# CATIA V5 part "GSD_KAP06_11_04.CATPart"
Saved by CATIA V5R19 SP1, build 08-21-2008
Part number: GSD_BLEND_05
Definition: Beispielmodell für die Funktion Übergang / Blend - Manuelle Verbindung.
Description: CATIA V5 Flächenmodellierung  Copyright (c) 2009 Maik Hertha IT Consultants
Bounding box of the stored display mesh (mm): x -164.511 to 102.98, y -20 to 224.611, z -30.362 to 44.999
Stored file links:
  \GSD_BUCH_UEBUNG\GSD_KAP06_11_04.CATPart
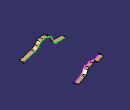
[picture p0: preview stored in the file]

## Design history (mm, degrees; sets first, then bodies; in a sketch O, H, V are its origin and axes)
AxisSystem1: origin (0, 0, 0), X (1, 0, 0), Y (0, 1, 0), Z (0, 0, 1)
Set1
  Sketch1 on ZX plane of AxisSystem1, origin (0, 0, 0), H (0, 0, 1), V (1, 0, 0)
    line L1 (-7.7811, 102.9804) -> (10.5771, 41.6998)
    arc A1 centre (44.1049, 51.744) radius 35 from (10.5771, 41.6998) to (24.809, 22.5435) ccw
    arc A2 centre (0, -15) radius 45 from (24.809, 22.5435) to (37.9923, 9.116) cw
    point P5 (0, -15)
    arc A3 centre (0, -15) radius 45 from (33.7014, -44.8197) to (4.0909, -59.8137) cw
    point P7 (0, -15)
    line L2 (-5, -69.7723) -> (-5, -121.1063)
    construction line L3 (70.2481, 0) -> (-64.8444, 0)
    point P8 (70.2481, 0)
    construction line L4 (0, 45.8622) -> (0, -41.9018)
    point P10 (0, 45.8622)
    curve C1
    arc A4 centre (5, -69.7723) radius 10 from (4.0909, -59.8137) to (-5, -69.7723) ccw
    arc A5 centre (0, -15) radius 45 from (37.9923, 9.116) to (43.6257, -3.9639) cw
    arc A6 centre (0, -15) radius 45 from (41.4452, -32.5298) to (33.7014, -44.8197) cw
    arc A7 centre (0, -15) radius 45 from (43.6257, -3.9639) to (41.4452, -32.5298) cw
    radius A3 = 45
    distance L4 L2 = 5
    distance P5 L3 = 15
    radius A4 = 10
    radius A1 = 35
    tangency: A1 L1, A2 A1, A3 A2, A4 L2, A4 A3
    vertical: L2 V, L4 V
    coincidence: P7 P5, P8 H, P10 V, P5 L4, A2 A5, A5 A6, A5 A7
    horizontal: L3 H
  Sketch2 on XY plane of AxisSystem1, origin (0, 0, 0), H (1, 0, 0), V (0, 1, 0)
    spline S1 through (63.5198, 0.6594) (52.4947, 108.5036) (27.7222, 201.6743)
    construction line L1 (63.5198, -33.9776) -> (63.5198, 23.4257)
    curve C1
    vertical: L1 V
  Plane1: type Normal, Curve Sketch2.C1, RefPoint {point type OnCurve, Support Sketch2.C1, Ratio 1}
  Sketch3 on Plane1, origin (27.7222, 201.6743, 0), H (-0.9497, -0.3131, 0), V (0, 0, 1)
    line L1 (-12.5925, -30.3622) -> (43.5645, -30.3622)
    line L2 (50.3453, -27.7121) -> (65.7944, -13.4594)
    line L3 (77.0077, -9.5205) -> (111.3244, -11.9105)
    line L4 (134.514, -21.3899) -> (139.6722, -25.7927)
    line L5 (149.4105, -29.3837) -> (195.8144, -29.3837)
    curve C1
    arc A1 centre (43.5645, -20.3622) radius 10 from (43.5645, -30.3622) to (50.3453, -27.7121) ccw
    arc A2 centre (75.9655, -24.4842) radius 15 from (65.7944, -13.4594) to (77.0077, -9.5205) cw
    arc A3 centre (108.5452, -51.8139) radius 40 from (111.3244, -11.9105) to (134.514, -21.3899) cw
    arc A4 centre (149.4105, -14.3837) radius 15 from (139.6722, -25.7927) to (149.4105, -29.3837) ccw
    radius A1 = 10
    radius A4 = 15
    radius A3 = 40
    radius A2 = 15
    horizontal: L1 H, L5 H
    tangency: A1 L1, A1 L2, A2 L2, A2 L3, A3 L3, A3 L4, A4 L4, A4 L5
  Extrude1: Lim1 20, Lim2 0, Element1 Sketch3.C1, Direction Plane1
  Extrude2: Lim1 20, Lim2 0, Element1 Sketch1.C1, Direction zx-plane
Body1 (main body)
